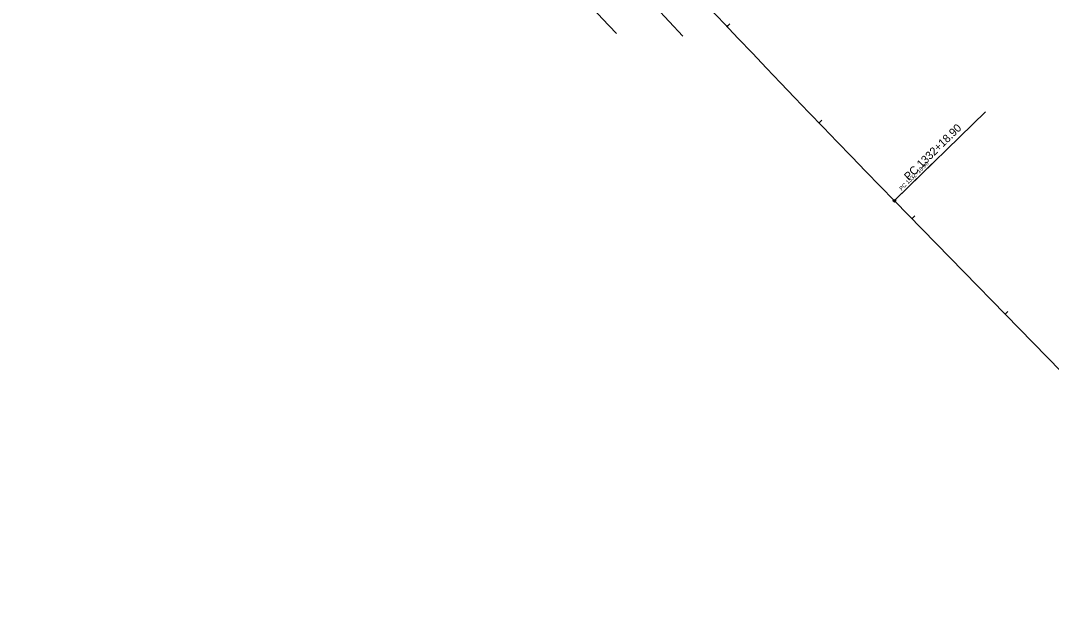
# Model space of a CAD drawing. Extents: x 2252205 to 2259955, y 13788514 to 13798103.
# Drawn here: x 2256266 to 2257039, y 13791365 to 13791797 of the extents above; entities that cross this region are included whole.
import ezdxf

# ---------------------------------------------------------------- set-up
doc = ezdxf.new("R2010")
doc.units = 0
for name, color, linetype in [('GEOM_CENTERLINE_ALIGN', 7, 'Continuous'), ('GEOM_CENTERLINE_PCPT_100', 7, 'Continuous'), ('GEOM_CENTERLINE_PCPT_50', 7, 'Continuous'), ('GEOM_CENTERLINE_STA_100', 7, 'Continuous'), ('GEOM_CENTERLINE_STA_50', 7, 'Continuous'), ('ROAD_ROW_PROPOSED', 7, 'Continuous'), ('TRAF_PAVMRK_W_4IN_SLD', 7, 'Continuous')]:
    doc.layers.add(name, color=color, linetype=linetype)

msp = doc.modelspace()

# ---------------------------------------------------------------- linework, layer by layer
at = {"layer": 'GEOM_CENTERLINE_ALIGN'}
msp.add_line((2259084.43, 13789447.87), (2256921.59, 13791662.1), dxfattribs=at)
msp.add_arc((2265119, 13799669.27), 11459.16, 219.418553, 224.327385, dxfattribs=at)
at = {"layer": 'GEOM_CENTERLINE_PCPT_100'}
msp.add_line((2256922.3, 13791662.8), (2256989.84, 13791728.76), dxfattribs=at)
at = {"layer": 'GEOM_CENTERLINE_PCPT_50'}
msp.add_line((2256921.94, 13791662.45), (2256955.71, 13791695.43), dxfattribs=at)
at = {"layer": 'GEOM_CENTERLINE_STA_100'}
for p, q in [((2256796.07, 13791792.65), (2256798.25, 13791794.71)), ((2256865.12, 13791720.32), (2256867.28, 13791722.4)), ((2256934.79, 13791648.58), (2256936.94, 13791650.68)), ((2257004.67, 13791577.04), (2257006.81, 13791579.14))]:
    msp.add_line(p, q, dxfattribs=at)
msp.add_circle((2256921.59, 13791662.1), 1, dxfattribs=at)
at = {"layer": 'GEOM_CENTERLINE_STA_50'}
for p, q in [((2256796.07, 13791792.65), (2256797.16, 13791793.68)), ((2256865.12, 13791720.32), (2256866.2, 13791721.36)), ((2256934.79, 13791648.58), (2256935.86, 13791649.63)), ((2257004.67, 13791577.04), (2257005.74, 13791578.09))]:
    msp.add_line(p, q, dxfattribs=at)
msp.add_circle((2256921.59, 13791662.1), 0.5, dxfattribs=at)
at = {"layer": 'ROAD_ROW_PROPOSED'}
msp.add_arc((2265116.03, 13799666.59), 11519.16, 220.67779, 223.158467, dxfattribs=at)
at = {"layer": 'TRAF_PAVMRK_W_4IN_SLD'}
msp.add_arc((2265119, 13799669.27), 11488.16, 220.923263, 223.335434, dxfattribs=at)

# ---------------------------------------------------------------- texts
at = {"layer": 'GEOM_CENTERLINE_PCPT_100'}
msp.add_text('PC 1332+18.90', height=6, rotation=44.32739, dxfattribs=at).set_placement((2256932.37, 13791676.82))
at = {"layer": 'GEOM_CENTERLINE_PCPT_50'}
msp.add_text('PC 1332+18.90', height=3, rotation=44.32739, dxfattribs=at).set_placement((2256926.98, 13791669.46))

doc.saveas('drawing.dxf')
